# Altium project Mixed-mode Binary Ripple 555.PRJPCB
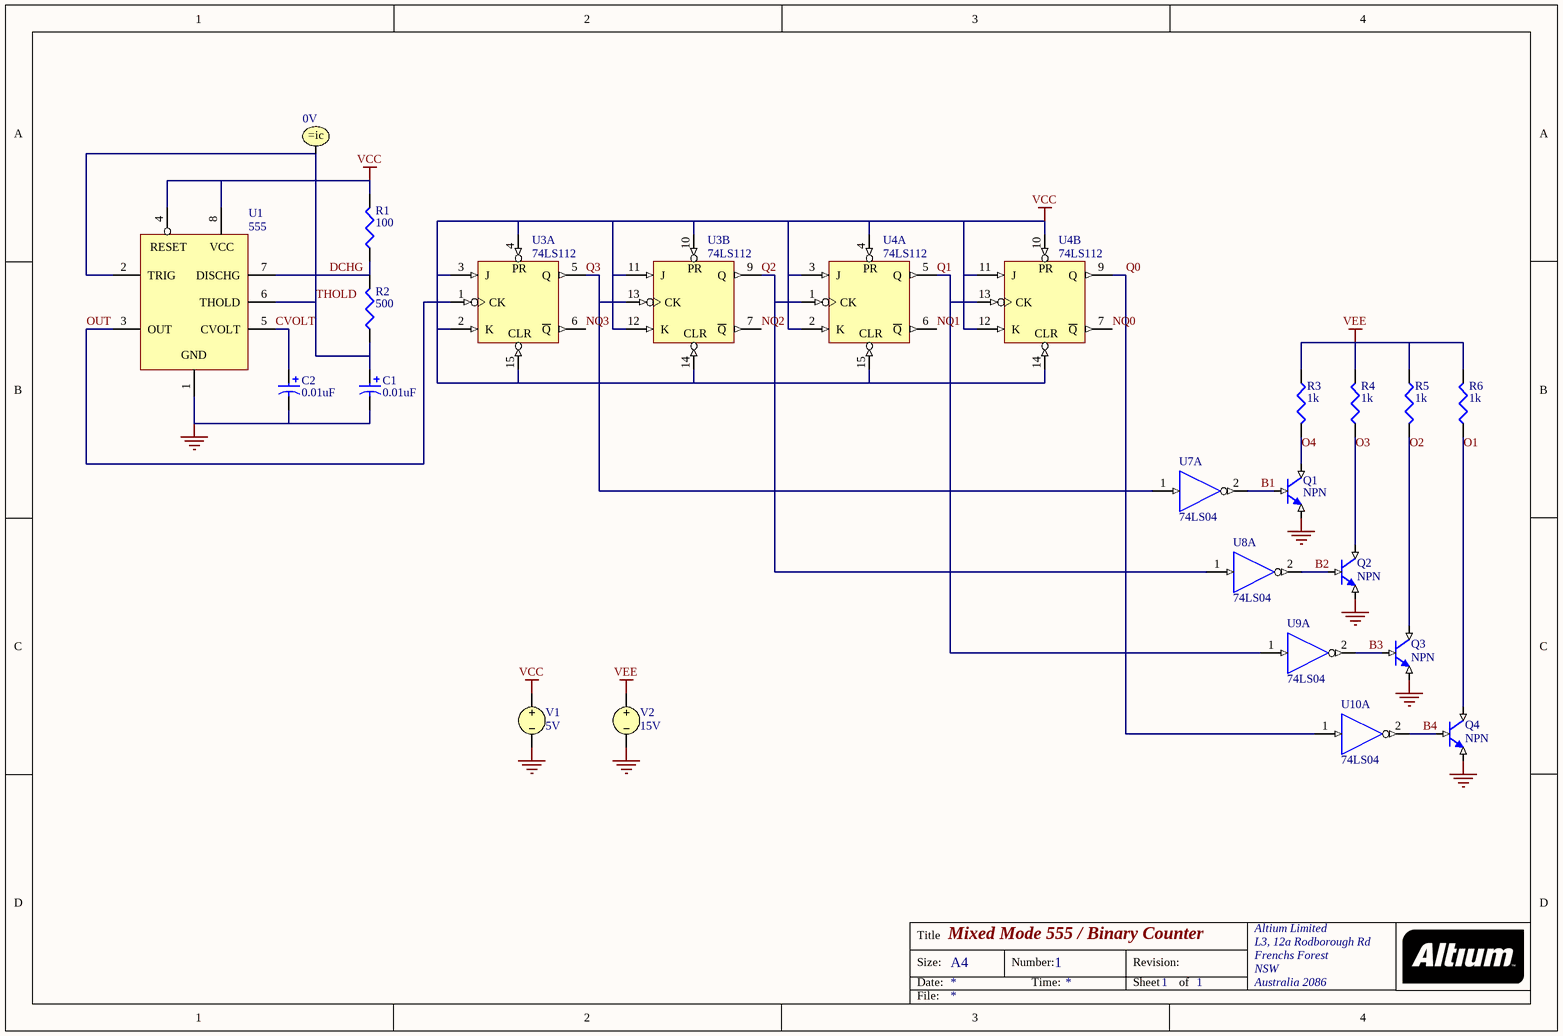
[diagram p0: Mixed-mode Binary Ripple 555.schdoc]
1 sheet, 22 parts. Net scope: global (net labels, ports and power ports of the same name join across sheets).

## Sheet Mixed-mode Binary Ripple 555.schdoc: Mixed Mode 555 / Binary Counter
size A4; Organization: Altium Limited; Address1: L3, 12a Rodborough Rd; Address2: Frenchs Forest; Address3: NSW; Address4: Australia 2086; DocumentNumber: 1; SheetNumber: 1; SheetTotal: 1

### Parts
C1  0.01uF
C2  0.01uF
IC1  0V
Q1  NPN
Q2  NPN
Q3  NPN
Q4  NPN
R1  100
R2  500
R3  1k
R4  1k
R5  1k
R6  1k
U1  555
U3  74LS112  (parts A,B of 2)
U4  74LS112  (parts A,B of 2)
U7  74LS04  (part A of 6)
U8  74LS04  (part A of 6)
U9  74LS04  (part A of 6)
U10  74LS04  (part A of 6)
V1  5V
V2  15V

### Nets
GND: C1.2 C2.2 Q1.3(E) Q2.3(E) Q3.3(E) Q4.3(E) U1.1(GND) U3.8(GND) U4.8(GND) U7.7(GND) U8.7(GND) U9.7(GND) U10.7(GND) V1.2 V2.2
VCC: R1.1(TOP) U1.4(RESET) U1.8(VCC) U3.2(K) U3.3(J) U3.4(PR) U3.10(PR) U3.11(J) U3.12(K) U3.14(CLR) U3.15(CLR) U3.16(VCC) U4.2(K) U4.3(J) U4.4(PR) U4.10(PR) U4.11(J) U4.12(K) U4.14(CLR) U4.15(CLR) U4.16(VCC) U7.14(VCC) U8.14(VCC) U9.14(VCC) U10.14(VCC) V1.1
VEE: R3.2(BOT) R4.1(TOP) R5.2(BOT) R6.1(TOP) V2.1
B1: Q1.2(B) U7.2(Y)
B2: Q2.2(B) U8.2(Y)
B3: Q3.2(B) U9.2(Y)
B4: Q4.2(B) U10.2(Y)
CVOLT: C2.1 U1.5(CVOLT)
DCHG: R1.2(BOT) R2.1(TOP) U1.7(DISCHG)
NQ0: U4.7(~{Q})
NQ1: U4.6(~{Q})
NQ2: U3.7(~{Q})
NQ3: U3.6(~{Q})
O1: Q4.1(C) R6.2(BOT)
O2: Q3.1(C) R5.1(TOP)
O3: Q2.1(C) R4.2(BOT)
O4: Q1.1(C) R3.1(TOP)
OUT: U1.3(OUT) U3.1(CK)
Q0: U4.9(Q) U10.1(A)
Q1: U4.5(Q) U4.13(CK) U9.1(A)
Q2: U3.9(Q) U4.1(CK) U8.1(A)
Q3: U3.5(Q) U3.13(CK) U7.1(A)
THOLD: C1.1 IC1.1 R2.2(BOT) U1.2(TRIG) U1.6(THOLD)

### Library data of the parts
C1 C2 = CAP2: Bi-Polar Capacitor
IC1 = .IC: Initial Condition
Q1-Q4 = NPN: NPN BJT
R1-R6 = RES: Resistor
U1 = 555: Timer
U3 U4 = 74LS112: Dual J-K Negative-Edge-Triggered Flip-Flop with Clear and Preset
U7-U10 = 74LS04: Hex Inverter
V1 V2 = VSRC: Voltage Source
